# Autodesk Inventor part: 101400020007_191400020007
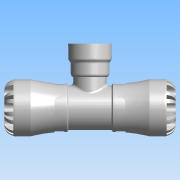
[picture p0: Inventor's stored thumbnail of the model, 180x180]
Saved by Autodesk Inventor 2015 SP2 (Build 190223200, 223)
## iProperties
Created: 2016-12
Part Number: 101400020007_191400020007
Material: PVC-Piping
Description: PLASSON TEE WITH THREADED FEMALE OFFTAKE 20X3/4" SERIES 1
Document SubType Name: Modeling
Designer: KIM
Mass: 664.223 g
Surface Area: 733.008 cm^2
Volume: 474.445 cm^3
Density: 1.4 g/cm^3
Appearance: Smooth - White
Author: KIM
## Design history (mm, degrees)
derived "1014.ipt"
feature "Solid1::1014.ipt"
tag "TaggingFeature1"
body "Solid1"
other parameters: "d1" = 18.9, "d3" = 25, "d4" = 41, "d8" = 34.85, "d13" = 6.4, "d14" = 6.4, "d15" = 0, "d17" = 360 deg, "d19" = 8 deg, "d20" = 0.4, "d21" = 0.4, "d22" = 8 deg, "d24" = 0, "d26" = 360 deg, "d33" = 4.1, "d43" = 31.98, "d51" = 0.41, "d54" = 7, "d55" = 4.4, "d57" = 12.544, "d58" = 0, "d74" = 0, "d77" = 1.66667, "d78" = 45, "d79" = 31.98, "d80" = 123, "d82" = 0.4, "d115" = 360 deg, "d139" = 6.4, "d140" = 0, "d142" = 360 deg, "d207" = 90 deg, "d228" = 5.95, "d247" = 0.82, "d248" = 2.7, "d266" = 0, "d268" = 24.117, "d270" = 3.61755, "d271" = 6, "d274" = 1.80878, "d275" = 46, "d276" = 2.4117, "d277" = 2.4117, "d278" = 2.4117, "d279" = 2.4117, "d281" = 0, "d282" = 18, "E_" = 41, "l_" = 45, "A_" = 46, "H_" = 123, "Rp_" = 24.117, "l_2" = 18, "d9" = 8, "d11" = 41, "d12" = 25
